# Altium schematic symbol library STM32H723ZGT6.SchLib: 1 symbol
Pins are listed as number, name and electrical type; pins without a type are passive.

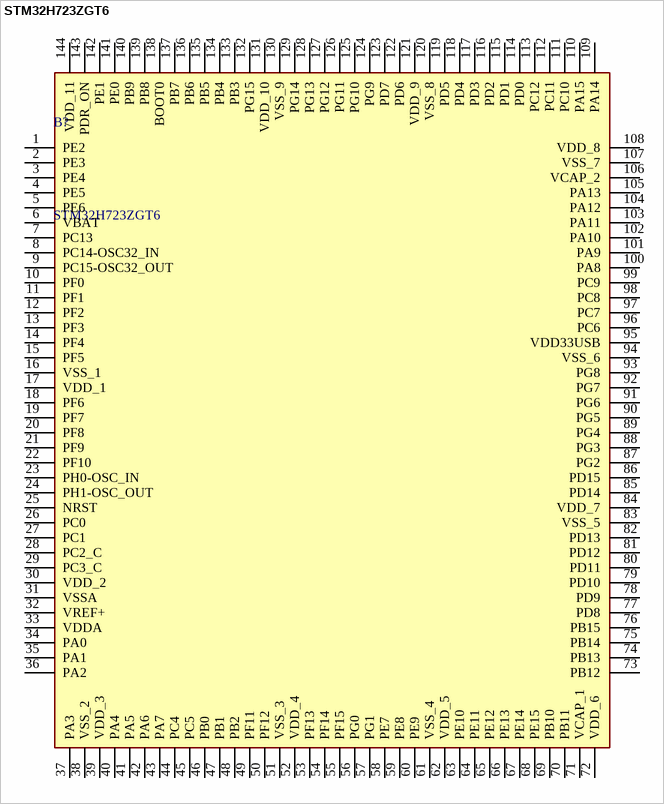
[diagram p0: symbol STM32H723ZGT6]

## STM32H723ZGT6
designator B?
Arm Cortex-M7 32-bit 550 MHz MCU, up to 1 MB Flash, 564KB RAM, Ethernet, USB, 3xFD-CAN, Graphics, 2x16-bit ADCs; Manufacturer_Name: STMicroelectronics; Geometry.Height: 1.6mm
footprint QFP50P2200X2200X160-144N
pins: 1 PE2, 2 PE3, 3 PE4, 4 PE5, 5 PE6, 6 VBAT, 7 PC13, 8 PC14-OSC32_IN, 9 PC15-OSC32_OUT, 10 PF0, 11 PF1, 12 PF2, 13 PF3, 14 PF4, 15 PF5, 16 VSS_1, 17 VDD_1, 18 PF6, 19 PF7, 20 PF8, 21 PF9, 22 PF10, 23 PH0-OSC_IN, 24 PH1-OSC_OUT, 25 NRST, 26 PC0, 27 PC1, 28 PC2_C, 29 PC3_C, 30 VDD_2, 31 VSSA, 32 VREF+, 33 VDDA, 34 PA0, 35 PA1, 36 PA2, 37 PA3, 38 VSS_2, 39 VDD_3, 40 PA4, 41 PA5, 42 PA6, 43 PA7, 44 PC4, 45 PC5, 46 PB0, 47 PB1, 48 PB2, 49 PF11, 50 PF12, 51 VSS_3, 52 VDD_4, 53 PF13, 54 PF14, 55 PF15, 56 PG0, 57 PG1, 58 PE7, 59 PE8, 60 PE9, 61 VSS_4, 62 VDD_5, 63 PE10, 64 PE11, 65 PE12, 66 PE13, 67 PE14, 68 PE15, 69 PB10, 70 PB11, 71 VCAP_1, 72 VDD_6, 73 PB12, 74 PB13, 75 PB14, 76 PB15, 77 PD8, 78 PD9, 79 PD10, 80 PD11, 81 PD12, 82 PD13, 83 VSS_5, 84 VDD_7, 85 PD14, 86 PD15, 87 PG2, 88 PG3, 89 PG4, 90 PG5, 91 PG6, 92 PG7, 93 PG8, 94 VSS_6, 95 VDD33USB, 96 PC6, 97 PC7, 98 PC8, 99 PC9, 100 PA8, 101 PA9, 102 PA10, 103 PA11, 104 PA12, 105 PA13, 106 VCAP_2, 107 VSS_7, 108 VDD_8, 109 PA14, 110 PA15, 111 PC10, 112 PC11, 113 PC12, 114 PD0, 115 PD1, 116 PD2, 117 PD3, 118 PD4, 119 PD5, 120 VSS_8, 121 VDD_9, 122 PD6, 123 PD7, 124 PG9, 125 PG10, 126 PG11, 127 PG12, 128 PG13, 129 PG14, 130 VSS_9, 131 VDD_10, 132 PG15, 133 PB3, 134 PB4, 135 PB5, 136 PB6, 137 PB7, 138 BOOT0, 139 PB8, 140 PB9, 141 PE0, 142 PE1, 143 PDR_ON, 144 VDD_11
